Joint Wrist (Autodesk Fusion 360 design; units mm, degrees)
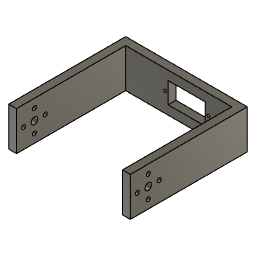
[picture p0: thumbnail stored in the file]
parameter "d5" = 115
sketch "Sketch1" plane through (0, 0, 0) normal (0, 0, 1) x axis (1, 0, 0)
  line L1 (5, 0) -> (0, 0)
  line L2 (5, 75) -> (5, 0)
  line L3 (0, 75) -> (5, 75)
  line L4 (0, 0) -> (0, 75)
  line L5 (73, 75) -> (5, 75)
  line L6 (73, 70) -> (73, 75)
  line L7 (5, 70) -> (73, 70)
  line L8 (5, 75) -> (5, 70)
  line L9 (78, 75) -> (73, 75)
  line L10 (78, 0) -> (78, 75)
  line L11 (73, 0) -> (78, 0)
  line L12 (73, 75) -> (73, 0)
  point P2 (0, 0)
  point P3 (5, 0)
  point P5 (0, 75)
  point P4 (5, 75)
  point P6 (73, 75)
  point P8 (5, 70)
  point P9 (78, 75)
  point P11 (73, 0)
  horizontal L1
  vertical L2
  horizontal L3
  vertical L4
  horizontal L5
  vertical L6
  horizontal L7
  vertical L8
  horizontal L9
  vertical L10
  horizontal L11
  vertical L12
  dimension "d73" distance P2 P3 = 5
  dimension "d74" distance P2 P5 = 75
  dimension "d75" distance P4 P6 = 68
  dimension "d76" distance P4 P8 = 5
  dimension "d77" distance P6 P9 = 5
  dimension "d78" distance P6 P11 = 75 (= "d74")
extrude "Extrude1" new body sketch "Sketch1" along normal blind 25
sketch "Sketch2" plane through (0, 0, 0) normal (1, 0, 0) x axis (0, 1, 0)
  line L1 (0, 0) -> (50, 0)
  line L2 (0, 25) -> (0, 0)
  line L3 (50, 25) -> (0, 25)
  line L4 (20, 12.5) -> (0, 12.5)
  line L5 (11.5, 12.5) -> (4.5, 12.5)
  line L6 (50, 0) -> (50, 25)
  line L7 (0, 0) -> (75, 0)
  line L8 (0, 25) -> (0, 0)
  line L9 (75, 25) -> (0, 25)
  line L10 (75, 0) -> (75, 25)
  circle C1 centre (4.5, 12.5) radius 1.3
  circle C2 centre (11.5, 5.5) radius 1.3
  circle C3 centre (18.5, 12.5) radius 1.3
  circle C4 centre (11.5, 19.5) radius 1.3
  circle C5 centre (11.5, 12.5) radius 2.15
  point P6 (0, 12.5)
  point P8 (4.5, 12.5)
  point P9 (4.5, 12.5)
  point P10 (11.5, 12.5)
  point P14 (11.5, 12.5)
  point P7 (20, 12.5)
  midpoint L2 P6
  perpendicular L2 L4
  coincident L4 P8
  coincident P8 P9
  parallel L4 L5
  coincident P10 P14
  dimension "d13" distance P6 P7 = 20
  dimension "d14" diameter C1 = 2.6
  dimension "d15" distance P9 P10 = 7
  dimension "d18" distance L2 P8 = 4.5
  dimension "d22" diameter C5 = 4.3
  dimension "d17" C-Pattern1-Angle = 360
extrude "Extrude3" cut sketch "Sketch2" profile of C1 C2 C3 C4 C5 along normal blind 78
sketch "Sketch7" plane through (0, 75, 0) normal (0, 1, 0) x axis (-1, 0, 0)
  line L1 (0, 0) -> (-78, 0)
  line L2 (0, 25) -> (0, 0)
  line L3 (-78, 25) -> (0, 25)
  line L4 (-78, 0) -> (-78, 25)
  line L5 (-54.55, 6.4) -> (-59.35, 6.4)
  line L6 (-54.55, 18.5) -> (-40.562, 18.5)
  line L7 (-40.562, 6.5) -> (-54.55, 6.5)
  line L8 (-33.75, 18.6) -> (-28.95, 18.6)
  line L9 (-33, 17.75) -> (-33, 14.062)
  line L10 (-60.2, 11.95) -> (-59.0026, 11.95)
  line L11 (-59.35, 18.6) -> (-54.55, 18.6)
  line L12 (-44.48, 15.4) -> (-44.6, 15.4)
  line L13 (-37.438, 18.5) -> (-33.75, 18.5)
  line L14 (-60.2, 13.05) -> (-60.2, 17.75)
  line L15 (-60.2, 7.25) -> (-60.2, 11.95)
  line L16 (-48.9, 17.6) -> (-53.9, 17.6)
  line L17 (-33, 10.938) -> (-33, 7.25)
  line L18 (-28.1, 17.75) -> (-28.1, 13.05)
  line L19 (-54.4, 17.1) -> (-54.4, 7.9)
  line L20 (-29.2974, 11.95) -> (-28.1, 11.95)
  line L21 (-28.1, 13.05) -> (-29.2974, 13.05)
  line L22 (-44.6, 15.2) -> (-44.48, 15.2)
  line L23 (-55.3, 7.25) -> (-55.3, 17.75)
  line L24 (-32.9, 7.25) -> (-32.9, 17.75)
  line L25 (-59.0026, 13.05) -> (-60.2, 13.05)
  line L26 (-28.95, 6.4) -> (-33.75, 6.4)
  line L27 (-53.9, 7.4) -> (-48.9, 7.4)
  line L28 (-48.4, 7.9) -> (-48.4, 17.1)
  line L29 (-44.6, 9.6) -> (-44.48, 9.6)
  line L30 (-55.4, 17.75) -> (-55.4, 7.25)
  line L31 (-33.75, 6.5) -> (-37.438, 6.5)
  line L32 (-28.1, 11.95) -> (-28.1, 7.25)
  line L33 (-44.48, 9.8) -> (-44.6, 9.8)
  line L34 (-78, 12.5) -> (0, 12.5)
  line L35 (-39, 25) -> (-39, 12.5)
  line L36 (-33.75, 17.75) -> (-54.55, 17.75)
  line L37 (-33.75, 7.25) -> (-33.75, 17.75)
  line L38 (-54.55, 7.25) -> (-33.75, 7.25)
  line L39 (-54.55, 17.75) -> (-54.55, 7.25)
  line L40 (-56.05, 5.75) -> (-32.25, 5.75)
  line L41 (-56.05, 19.25) -> (-56.05, 5.75)
  line L42 (-32.25, 19.25) -> (-56.05, 19.25)
  line L43 (-32.25, 5.75) -> (-32.25, 19.25)
  circle C1 centre (-39, 12.5) radius 2.25
  circle C2 centre (-39, 12.5) radius 0.8
  arc A1 centre (-59.35, 17.75) radius 0.85 clockwise from (-60.2, 17.75) to (-59.35, 18.6)
  arc A2 centre (-44.6, 12.5) radius 2.7 clockwise from (-44.6, 9.8) to (-44.6, 15.2)
  circle C3 centre (-39, 12.5) radius 0.8
  arc A3 centre (-39, 12.5) radius 6.2 clockwise from (-44.48, 15.4) to (-40.562, 18.5)
  arc A4 centre (-59.35, 7.25) radius 0.85 clockwise from (-59.35, 6.4) to (-60.2, 7.25)
  arc A5 centre (-39, 12.5) radius 6 clockwise from (-44.3032, 15.3065) to (-44.3032, 9.6935)
  circle C4 centre (-39, 12.5) radius 2.5
  arc A6 centre (-33.75, 17.75) radius 0.75 clockwise from (-33.75, 18.5) to (-33, 17.75)
  arc A7 centre (-53.9, 7.9) radius 0.5 clockwise from (-53.9, 7.4) to (-54.4, 7.9)
  arc A8 centre (-33.75, 7.25) radius 0.85 clockwise from (-32.9, 7.25) to (-33.75, 6.4)
  arc A9 centre (-39, 12.5) radius 6.2 clockwise from (-37.438, 18.5) to (-33, 14.062)
  arc A10 centre (-30.25, 12.5) radius 1.1 clockwise from (-29.2974, 11.95) to (-29.2974, 13.05)
  arc A11 centre (-44.48, 9.6) radius 0.2 clockwise from (-44.48, 9.8) to (-44.3032, 9.6935)
  circle C5 centre (-39, 12.5) radius 2.25
  arc A12 centre (-53.9, 17.1) radius 0.5 clockwise from (-54.4, 17.1) to (-53.9, 17.6)
  arc A13 centre (-33.75, 17.75) radius 0.85 clockwise from (-33.75, 18.6) to (-32.9, 17.75)
  arc A14 centre (-48.9, 17.1) radius 0.5 clockwise from (-48.9, 17.6) to (-48.4, 17.1)
  arc A15 centre (-39, 12.5) radius 6.2 clockwise from (-33, 10.938) to (-37.438, 6.5)
  arc A16 centre (-39, 12.5) radius 6.2 clockwise from (-40.562, 6.5) to (-44.48, 9.6)
  arc A17 centre (-54.55, 7.25) radius 0.85 clockwise from (-54.55, 6.4) to (-55.4, 7.25)
  arc A18 centre (-58.05, 12.5) radius 1.1 clockwise from (-59.0026, 13.05) to (-59.0026, 11.95)
  arc A19 centre (-28.95, 7.25) radius 0.85 clockwise from (-28.1, 7.25) to (-28.95, 6.4)
  arc A20 centre (-44.6, 12.5) radius 2.9 clockwise from (-44.6, 9.6) to (-44.6, 15.4)
  arc A21 centre (-33.75, 7.25) radius 0.75 clockwise from (-33, 7.25) to (-33.75, 6.5)
  arc A22 centre (-44.48, 15.4) radius 0.2 clockwise from (-44.3032, 15.3065) to (-44.48, 15.2)
  arc A23 centre (-54.55, 17.75) radius 0.85 clockwise from (-55.4, 17.75) to (-54.55, 18.6)
  arc A24 centre (-28.95, 17.75) radius 0.85 clockwise from (-28.95, 18.6) to (-28.1, 17.75)
  arc A25 centre (-54.55, 7.25) radius 0.75 clockwise from (-54.55, 6.5) to (-55.3, 7.25)
  arc A26 centre (-48.9, 7.9) radius 0.5 clockwise from (-48.4, 7.9) to (-48.9, 7.4)
  arc A27 centre (-54.55, 17.75) radius 0.75 clockwise from (-55.3, 17.75) to (-54.55, 18.5)
  circle C6 centre (-58.05, 12.5) radius 0.9
  circle C7 centre (-30.25, 12.5) radius 0.9
  point P92 (0, 12.5)
  point P93 (-78, 12.5)
  point P94 (-39, 12.5)
  point P95 (-39, 25)
  point P50 (-33.75, 7.25)
  point P100 (-33.75, 7.25)
  point P89 (-54.55, 17.75)
  point P98 (-54.55, 17.75)
  midpoint L2 P92
  midpoint L4 P93
  midpoint L34 P94
  midpoint L3 P95
  concentric A18 C6
  concentric A10 C7
  horizontal L36
  vertical L37
  horizontal L38
  vertical L39
  coincident P50 P100
  coincident P89 P98
  dimension "d79" diameter C6 = 1.8
  dimension "d80" diameter C7 = 1.8 (= "d79")
  dimension "d81" = -1.5
extrude "Extrude7" cut sketch "Sketch7" profile of C6 C7 L41 L40 L42 L43 to an object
